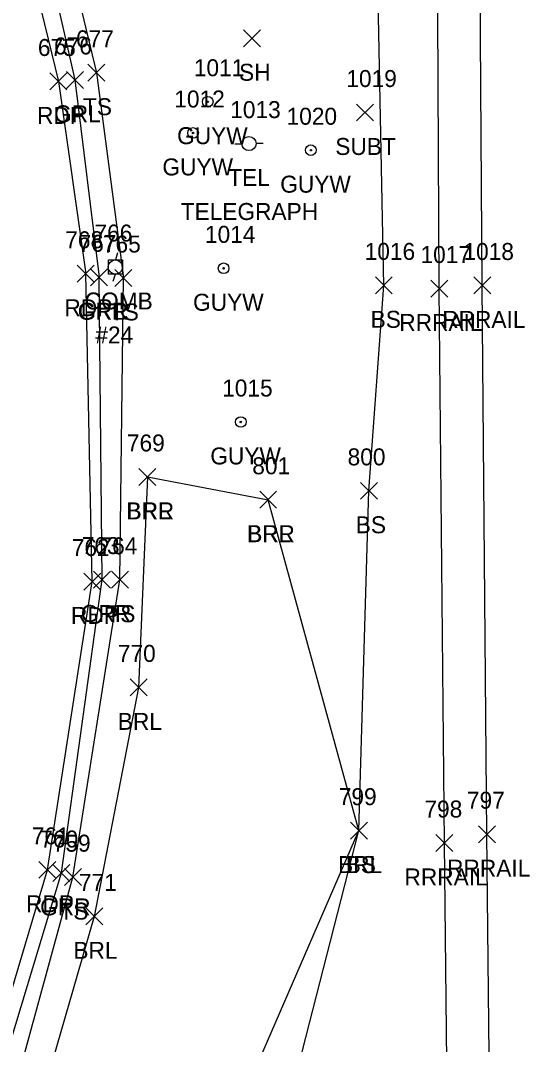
# Model space of a CAD drawing. Extents: x 1764889 to 1767296, y 695936 to 698960.
# Drawn here: x 1766359.5 to 1766419.5, y 696396.7 to 696517.3 of the extents above; entities that cross this region are included whole.
import ezdxf

# ---------------------------------------------------------------- set-up
doc = ezdxf.new("R2010")
doc.units = 0
for name, color, linetype in [('L_A', 7, 'Continuous'), ('L_I', 7, 'Continuous'), ('L_TIC', 7, 'Continuous'), ('LABL', 7, 'Continuous'), ('LELB', 7, 'Continuous'), ('P_A', 7, 'Continuous'), ('P_I', 7, 'Continuous'), ('P_TIC', 7, 'Continuous'), ('PET', 7, 'Continuous'), ('R_A', 7, 'Continuous'), ('R_I', 7, 'Continuous'), ('R_TIC', 7, 'Continuous'), ('RGR', 7, 'Continuous'), ('RR', 7, 'Continuous'), ('U_A', 7, 'Continuous'), ('U_C', 7, 'Continuous'), ('U_I', 7, 'Continuous'), ('U_TIC', 7, 'Continuous'), ('UP', 7, 'Continuous'), ('UPGW', 7, 'Continuous')]:
    doc.layers.add(name, color=color, linetype=linetype)

msp = doc.modelspace()

# ---------------------------------------------------------------- linework, layer by layer
at = {"layer": 'L_TIC'}
for points in [[(1766385.78, 696514.23), (1766387.78, 696516.23)], [(1766387.78, 696514.23), (1766385.78, 696516.23)], [(1766367.46, 696510.17), (1766369.46, 696512.17)], [(1766369.46, 696510.17), (1766367.46, 696512.17)], [(1766370.63, 696486), (1766372.63, 696488)], [(1766372.63, 696486), (1766370.63, 696488)], [(1766370.63, 696486), (1766372.63, 696488)], [(1766372.63, 696486), (1766370.63, 696488)], [(1766401.32, 696485.13), (1766403.32, 696487.13)], [(1766403.32, 696485.13), (1766401.32, 696487.13)], [(1766373.47, 696462.57), (1766375.47, 696464.57)], [(1766375.47, 696462.57), (1766373.47, 696464.57)], [(1766373.47, 696462.57), (1766375.47, 696464.57)], [(1766375.47, 696462.57), (1766373.47, 696464.57)], [(1766399.57, 696460.93), (1766401.57, 696462.93)], [(1766401.57, 696460.93), (1766399.57, 696462.93)], [(1766387.69, 696459.88), (1766389.69, 696461.88)], [(1766389.69, 696459.88), (1766387.69, 696461.88)], [(1766387.69, 696459.88), (1766389.69, 696461.88)], [(1766389.69, 696459.88), (1766387.69, 696461.88)], [(1766370.22, 696450.45), (1766372.22, 696452.45)], [(1766372.22, 696450.45), (1766370.22, 696452.45)], [(1766372.43, 696437.78), (1766374.43, 696439.78)], [(1766374.43, 696437.78), (1766372.43, 696439.78)], [(1766398.38, 696420.91), (1766400.38, 696422.91)], [(1766400.38, 696420.91), (1766398.38, 696422.91)], [(1766398.38, 696420.91), (1766400.38, 696422.91)], [(1766400.38, 696420.91), (1766398.38, 696422.91)], [(1766364.68, 696415.43), (1766366.68, 696417.43)], [(1766366.68, 696415.43), (1766364.68, 696417.43)], [(1766367.2, 696410.81), (1766369.2, 696412.81)], [(1766369.2, 696410.81), (1766367.2, 696412.81)]]:
    msp.add_lwpolyline(points, dxfattribs=at)
at = {"layer": 'LABL'}
for points in [[(1766374.47, 696463.57), (1766373.43, 696438.78), (1766368.2, 696411.81), (1766360.84, 696386.39), (1766351.73, 696360.89), (1766343.31, 696345.27)], [(1766374.47, 696463.57), (1766388.69, 696460.88)], [(1766386.9, 696373.17), (1766399.38, 696421.91), (1766388.69, 696460.88)]]:
    msp.add_lwpolyline(points, dxfattribs=at)
at = {"layer": 'LELB'}
for points in [[(1766376.43, 696369.05), (1766399.38, 696421.91), (1766400.57, 696461.93), (1766402.32, 696486.13), (1766401.07, 696549.52), (1766401.07, 696591.37), (1766401.28, 696644.9)], [(1766348.57, 696576.19), (1766359.01, 696560.03), (1766361.49, 696540.26), (1766368.46, 696511.17), (1766371.63, 696487)], [(1766335.34, 696344.42), (1766347.08, 696362.86), (1766357.68, 696387.14), (1766365.68, 696416.43), (1766371.22, 696451.45), (1766371.63, 696487)]]:
    msp.add_lwpolyline(points, dxfattribs=at)
at = {"layer": 'P_TIC'}
for points in [[(1766362.97, 696509.15), (1766364.97, 696511.15)], [(1766364.97, 696509.15), (1766362.97, 696511.15)], [(1766366.19, 696486.5), (1766368.19, 696488.5)], [(1766368.19, 696486.5), (1766366.19, 696488.5)], [(1766366.19, 696486.5), (1766368.19, 696488.5)], [(1766368.19, 696486.5), (1766366.19, 696488.5)], [(1766366.96, 696450.25), (1766368.96, 696452.25)], [(1766368.96, 696450.25), (1766366.96, 696452.25)], [(1766361.68, 696416.29), (1766363.68, 696418.29)], [(1766363.68, 696416.29), (1766361.68, 696418.29)]]:
    msp.add_lwpolyline(points, dxfattribs=at)
at = {"layer": 'PET'}
for points in [[(1766331.65, 696550.27), (1766338.9, 696564.49), (1766345.39, 696577.08), (1766352.15, 696555.7), (1766356.95, 696538.79), (1766363.97, 696510.15), (1766367.19, 696487.5)], [(1766331.65, 696550.27), (1766337.19, 696529.87), (1766342.79, 696505.62), (1766343.93, 696497.35), (1766345.9, 696477.35), (1766345.61, 696451.13), (1766342.46, 696428.54), (1766337.12, 696406.59), (1766328.57, 696382.86), (1766317.54, 696359.04), (1766312, 696349.5), (1766322.36, 696346.4), (1766331.24, 696344.36), (1766343.78, 696364.8), (1766353.91, 696387.85), (1766362.68, 696417.29), (1766367.96, 696451.25), (1766367.19, 696487.5)]]:
    msp.add_lwpolyline(points, dxfattribs=at)
at = {"layer": 'R_TIC'}
for points in [[(1766364.92, 696509.33), (1766366.92, 696511.33)], [(1766366.92, 696509.33), (1766364.92, 696511.33)], [(1766367.76, 696486.08), (1766369.76, 696488.08)], [(1766369.76, 696486.08), (1766367.76, 696488.08)], [(1766367.76, 696486.08), (1766369.76, 696488.08)], [(1766369.76, 696486.08), (1766367.76, 696488.08)], [(1766407.85, 696484.76), (1766409.85, 696486.76)], [(1766409.85, 696484.76), (1766407.85, 696486.76)], [(1766412.91, 696485.12), (1766414.91, 696487.12)], [(1766414.91, 696485.12), (1766412.91, 696487.12)], [(1766368.13, 696450.48), (1766370.13, 696452.48)], [(1766370.13, 696450.48), (1766368.13, 696452.48)], [(1766408.46, 696419.45), (1766410.46, 696421.45)], [(1766410.46, 696419.45), (1766408.46, 696421.45)], [(1766413.47, 696420.49), (1766415.47, 696422.49)], [(1766415.47, 696420.49), (1766413.47, 696422.49)], [(1766363.33, 696415.92), (1766365.33, 696417.92)], [(1766365.33, 696415.92), (1766363.33, 696417.92)]]:
    msp.add_lwpolyline(points, dxfattribs=at)
at = {"layer": 'RGR'}
for points in [[(1766346.64, 696575.95), (1766353.71, 696555.93), (1766359.06, 696540.35), (1766365.92, 696510.33), (1766368.76, 696487.08)], [(1766333.29, 696344.42), (1766345.06, 696363.98), (1766355.56, 696387.92), (1766364.33, 696416.92), (1766369.13, 696451.48), (1766368.76, 696487.08)]]:
    msp.add_lwpolyline(points, dxfattribs=at)
at = {"layer": 'RR'}
for points in [[(1766410.41, 696332.08), (1766409.46, 696420.45), (1766408.85, 696485.76), (1766408.53, 696550.3), (1766408.18, 696590.82), (1766408.03, 696642.92), (1766408.33, 696712.56), (1766409.02, 696750.78), (1766409.91, 696798.98)], [(1766415.4, 696332.21), (1766414.47, 696421.49), (1766413.91, 696486.12), (1766413.47, 696550.63), (1766413.06, 696590.68), (1766412.95, 696642.7), (1766413.23, 696713.18), (1766413.82, 696750.29), (1766414.9, 696799.38)]]:
    msp.add_lwpolyline(points, dxfattribs=at)
at = {"layer": 'U_TIC'}
for points in [[(1766399.11, 696505.49), (1766401.11, 696507.49)], [(1766401.11, 696505.49), (1766399.11, 696507.49)]]:
    msp.add_lwpolyline(points, dxfattribs=at)
at = {"layer": 'UP'}
for p, q in [((1766384.77, 696502.82), (1766385.59, 696502.82)), ((1766386.43, 696502.83), (1766386.43, 696502.83)), ((1766388.09, 696502.83), (1766387.26, 696502.83)), ((1766387.26, 696502.83), (1766387.26, 696502.83)), ((1766388.09, 696502.83), (1766388.09, 696502.83)), ((1766369.86, 696487.45), (1766369.86, 696489.12)), ((1766369.86, 696489.12), (1766371.52, 696489.12)), ((1766370.94, 696489.95), (1766370.69, 696489.12)), ((1766371.52, 696489.12), (1766371.52, 696487.45)), ((1766370.69, 696488.29), (1766370.69, 696488.29)), ((1766371.52, 696487.45), (1766369.86, 696487.45)), ((1766370.44, 696486.62), (1766370.69, 696487.45))]:
    msp.add_line(p, q, dxfattribs=at)
for centre in [(1766386.43, 696502.83), (1766370.69, 696488.29)]:
    msp.add_circle(centre, 0.833, dxfattribs=at)
at = {"layer": 'UPGW'}
for centre, radius in [((1766381.57, 696507.76), 0.625), ((1766381.57, 696507.76), 0.0833), ((1766379.84, 696504.08), 0.625), ((1766379.84, 696504.08), 0.0833), ((1766393.72, 696502.05), 0.625), ((1766393.72, 696502.05), 0.0833), ((1766383.44, 696488.14), 0.625), ((1766383.44, 696488.14), 0.0833), ((1766385.47, 696470.04), 0.625), ((1766385.47, 696470.04), 0.0833)]:
    msp.add_circle(centre, radius, dxfattribs=at)

# ---------------------------------------------------------------- texts
at = {"layer": 'L_A'}
for s, p in [('SH', (1766385.26, 696510.23)), ('TS', (1766366.87, 696506.17)), ('TS', (1766370.04, 696482)), ('TS', (1766370.04, 696482)), ('BS', (1766400.76, 696481.13)), ('BRR', (1766371.96, 696458.57)), ('BRL', (1766372.01, 696458.57)), ('BS', (1766399.01, 696456.93)), ('BRR', (1766386.18, 696455.88)), ('BRL', (1766386.23, 696455.88)), ('TS', (1766369.63, 696446.45)), ('BRL', (1766370.97, 696433.78)), ('BRL', (1766396.92, 696416.91)), ('BS', (1766397.82, 696416.91)), ('TS', (1766364.09, 696411.43)), ('BRL', (1766365.74, 696406.81))]:
    msp.add_text(s, height=2, dxfattribs=at).set_placement(p)
at = {"layer": 'L_I'}
for s, p in [('677', (1766366.05, 696514.17)), ('765', (1766369.22, 696490)), ('765', (1766369.22, 696490)), ('1016', (1766400.06, 696489.13)), ('769', (1766372.05, 696466.57)), ('769', (1766372.05, 696466.57)), ('800', (1766398.05, 696464.93)), ('801', (1766386.82, 696463.88)), ('801', (1766386.82, 696463.88)), ('764', (1766368.81, 696454.45)), ('770', (1766370.98, 696441.78)), ('799', (1766397.01, 696424.91)), ('799', (1766397.01, 696424.91)), ('759', (1766363.31, 696419.43)), ('771', (1766366.4, 696414.81))]:
    msp.add_text(s, height=2, dxfattribs=at).set_placement(p)
at = {"layer": 'P_A'}
for p in [(1766361.46, 696505.15), (1766364.68, 696482.5), (1766364.68, 696482.5), (1766365.45, 696446.25), (1766360.17, 696412.29)]:
    msp.add_text('RDP', height=2, dxfattribs=at).set_placement(p)
at = {"layer": 'P_I'}
for s, p in [('675', (1766361.56, 696513.15)), ('768', (1766364.78, 696490.5)), ('768', (1766364.78, 696490.5)), ('762', (1766365.55, 696454.25)), ('761', (1766360.83, 696420.29))]:
    msp.add_text(s, height=2, dxfattribs=at).set_placement(p)
at = {"layer": 'R_A'}
for s, p in [('GRL', (1766363.47, 696505.33)), ('GRR', (1766366.25, 696482.08)), ('GRL', (1766366.31, 696482.08)), ('RRRAIL', (1766409.2, 696481.12)), ('RRRAIL', (1766404.14, 696480.76)), ('GRR', (1766366.62, 696446.48)), ('RRRAIL', (1766409.77, 696416.49)), ('RRRAIL', (1766404.75, 696415.45)), ('GRR', (1766361.82, 696411.92))]:
    msp.add_text(s, height=2, dxfattribs=at).set_placement(p)
at = {"layer": 'R_I'}
for s, p in [('676', (1766363.46, 696513.33)), ('767', (1766366.35, 696490.08)), ('767', (1766366.35, 696490.08)), ('1017', (1766406.64, 696488.76)), ('1018', (1766411.7, 696489.12)), ('763', (1766366.72, 696454.48)), ('797', (1766412.11, 696424.49)), ('798', (1766407.1, 696423.45)), ('760', (1766361.84, 696419.92))]:
    msp.add_text(s, height=2, dxfattribs=at).set_placement(p)
at = {"layer": 'U_A'}
for s, p in [('GUYW', (1766377.96, 696502.76)), ('SUBT', (1766396.6, 696501.49)), ('GUYW', (1766376.23, 696499.08)), ('TEL', (1766383.98, 696497.83)), ('GUYW', (1766390.11, 696497.05)), ('COMB', (1766367.07, 696483.29)), ('GUYW', (1766379.84, 696483.14)), ('GUYW', (1766381.87, 696465.04))]:
    msp.add_text(s, height=2, dxfattribs=at).set_placement(p)
at = {"layer": 'U_C'}
for s, p in [('TELEGRAPH', (1766378.38, 696493.83)), ('#24', (1766368.33, 696479.29))]:
    msp.add_text(s, height=2, dxfattribs=at).set_placement(p)
at = {"layer": 'U_I'}
for s, p in [('1011', (1766379.93, 696510.76)), ('1019', (1766397.9, 696509.49)), ('1012', (1766377.63, 696507.08)), ('1013', (1766384.22, 696505.83)), ('1020', (1766390.86, 696505.05)), ('766', (1766368.22, 696491.29)), ('1014', (1766381.24, 696491.14)), ('1015', (1766383.27, 696473.04))]:
    msp.add_text(s, height=2, dxfattribs=at).set_placement(p)

doc.saveas('drawing.dxf')
